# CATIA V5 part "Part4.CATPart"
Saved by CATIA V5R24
Part number: Part4
Bounding box of the stored display mesh (mm): x -20 to 40, y 0 to 80, z 0 to 220
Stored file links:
  G:\_CAD수업\DMU_paradoxes\inversion\Part4.CATPart
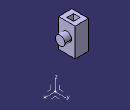
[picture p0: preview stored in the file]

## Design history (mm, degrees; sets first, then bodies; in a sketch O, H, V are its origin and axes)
AxisSystem1: origin (0, 0, 0), X (1, 0, 0), Y (0, 1, 0), Z (0, 0, 1)
Set1
  Sketch1 on YZ plane of AxisSystem1, origin (0, 0, 0), H (0, 1, 0), V (0, 0, 1)
    line L1 (30, 220) -> (80, 220)
    line L2 (80, 220) -> (80, 135)
    line L3 (80, 135) -> (30, 135)
    line L4 (30, 135) -> (30, 220)
    horizontal: L1 H, L3 H
    vertical: L2 V, L4 V
Body1 (main body)
  Pad1: profile Sketch1, direction (1, 0, 0), length 20, mirrored extent
  Sketch2 on face of Pad1 from Sketch1.L1, origin (0, 0, 220), H (1, 0, 0), V (0, 1, 0)
    line L1 (-10, 65) -> (10, 65)
    line L2 (10, 65) -> (10, 45)
    line L3 (10, 45) -> (-10, 45)
    line L4 (-10, 45) -> (-10, 65)
    horizontal: L1 H, L3 H
    vertical: L2 V, L4 V
  Pocket1: profile Sketch2, direction (0, 0, -1), through (limit type 6)
  Sketch3 on end face of Pad1, origin (20, 0, 0), H (0, 1, 0), V (0, 0, 1)
    circle A1 centre (55, 180) radius 14.1421
  Pad2: profile Sketch3, direction (1, 0, 0), length 20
